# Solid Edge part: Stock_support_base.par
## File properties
Title: Solid Edge 20
Author: vicky raina
Template: Normal.par
Last saved by: Robert a Rhodes jr
Revision: 17
Application: Solid Edge
Material: aluminum
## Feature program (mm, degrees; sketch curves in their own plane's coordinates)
sketch for "unnamed RevolvedProtrusion 1" plane through (0, 0, 0) normal (0, -1, 0) x-axis (1, 0, 0)
  line (0, 29.2468) -> (71.7103, 29.2468)
  line (71.7103, 29.2468) -> (71.7103, 19.7218)
  line (71.7103, 19.7218) -> (165.1, -256.5032)
  line (165.1, -256.5032) -> (215.9, -256.5032)
  line (215.9, -256.5032) -> (215.9, -281.9032)
  line (215.9, -281.9032) -> (156.9298, -281.9032)
  line (156.9298, -281.9032) -> (85.052, -69.3053)
  arc centre (73.021, -73.3729) radius 12.7 from (60.325, -73.0538) to (85.052, -69.3053) cw
  line (60.325, -73.0538) -> (57.15, -199.3532)
  line (57.15, -199.3532) -> (0, -199.3532)
  line (0, 29.2468) -> (0, -199.3532)
revolve "unnamed RevolvedProtrusion 1" add full turn 360 deg
sketch for "unnamed Hole 1" plane through (0, 0, 29.2468) normal (0, 0, 1) x-axis (1, 0, 0)
  hole centre (0, 0) bore radius 38.1
hole "unnamed Hole 1" through
sketch for "unnamed Protrusion 1" plane through (0, 0, -256.5032) normal (0, 0, 1) x-axis (0, 1, 0)
  arc centre (0, -119.2664) radius 41.0756 from (-18.7686, -155.8034) to (18.7686, -155.8034) ccw
  line (-18.7686, -197.1314) -> (-18.7686, -155.8034)
  arc centre (0, -197.1314) radius 18.7686 from (18.7686, -197.1314) to (-18.7686, -197.1314) cw
  line (18.7686, -197.1314) -> (18.7686, -155.8034)
extrude "unnamed Protrusion 1" add finite 12.7 along +normal
sketch for "unnamed Hole 2" plane through (187.8036, 0, -243.8032) normal (0, 0, 1) x-axis (1, 0, 0)
hole "unnamed Hole 2" through
fillet "unnamed Round 1"
pattern "unnamed Pattern 1" of "unnamed Protrusion 1", "unnamed Hole 2", "unnamed Round 1"
pattern "unnamed Pattern 2"
sketch for "unnamed Protrusion 2" plane through (0, -134.62, 0) normal (0, -1, 0) x-axis (1, 0, 0)
  circle centre (0, -2.5032) radius 19.05
extrude "unnamed Protrusion 2" add
adv blend "unnamed AdvBlend 1"
sketch for "unnamed Protrusion 3" plane through (0, -134.62, -2.5032) normal (0, -1, 0) x-axis (1, 0, 0)
  circle centre (0, -3.81) radius 22.225
extrude "unnamed Protrusion 3" add finite 9.525 along +normal
mirror "unnamed Mirror 1" of "unnamed Protrusion 3", "unnamed AdvBlend 1", "unnamed Protrusion 2" about plane through (0, 0, 0) normal (0, -1, 0)
extrude "unnamed Protrusion 4" add
adv blend "unnamed AdvBlend 2"
extrude "unnamed Protrusion 5" add finite 9.525
sketch for "unnamed Protrusion 6" plane through (104.775, 0, 0) normal (1, 0, 0) x-axis (0, 1, 0)
  circle centre (0, -167.6032) radius 19.05
extrude "unnamed Protrusion 6" add finite 41.275 along +normal
sketch for "unnamed Hole 3" plane through (146.05, 0, -167.6032) normal (1, 0, 0) x-axis (0, 1, 0)
  hole centre (0, 0) bore radius 7.9375
hole "unnamed Hole 3" through
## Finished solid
Body 1: solid body, 54 faces, 95 edges, 41 vertices.
  Faces by surface: plane 26, cylinder 19, torus 4, cone 3, blend 2
  Edges by curve: circle 57, intersection 20, line 18
Bounding box of the edges (mm; curved faces can reach further): 431.800 x 431.800 x 311.150, from (-215.9, -215.9, -281.9032) to (215.9, 215.9, 29.2468).
Cylindrical faces by radius (mm): R7.9375 x1, R11.1125 x3, R15.875 x3, R18.7686 x3, R19.05 x4, R22.225 x2, R38.1 x1, R71.7103 x1, R215.9 x1
Conical faces (half-angle, radius in mm at the cone's reference point): 1.44 deg R60.325 x1, 18.68 deg R71.7103 x1, 18.68 deg R156.9298 x1
Toroidal faces (ring radius, tube radius in mm): R73.021 r12.7 x1, R163.0843 r3.175 x3
Planar faces by outward normal: +x 1, +y 4, +z 10, -x 1, -y 4, -z 2, oblique 4
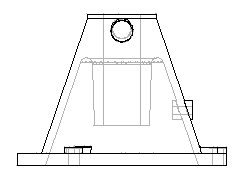
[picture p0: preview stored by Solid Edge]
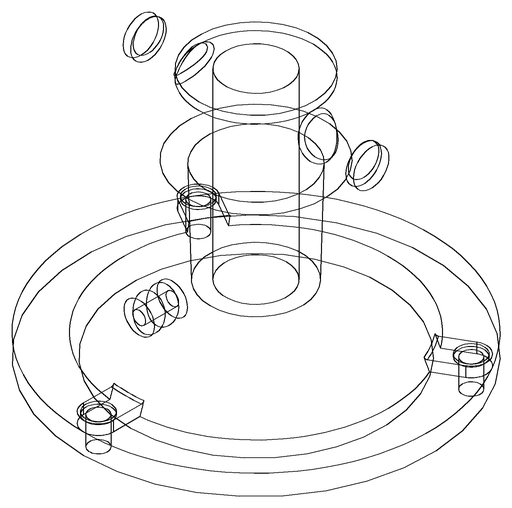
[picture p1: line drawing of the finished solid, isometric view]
